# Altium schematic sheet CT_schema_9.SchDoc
size 308 x 210 mm
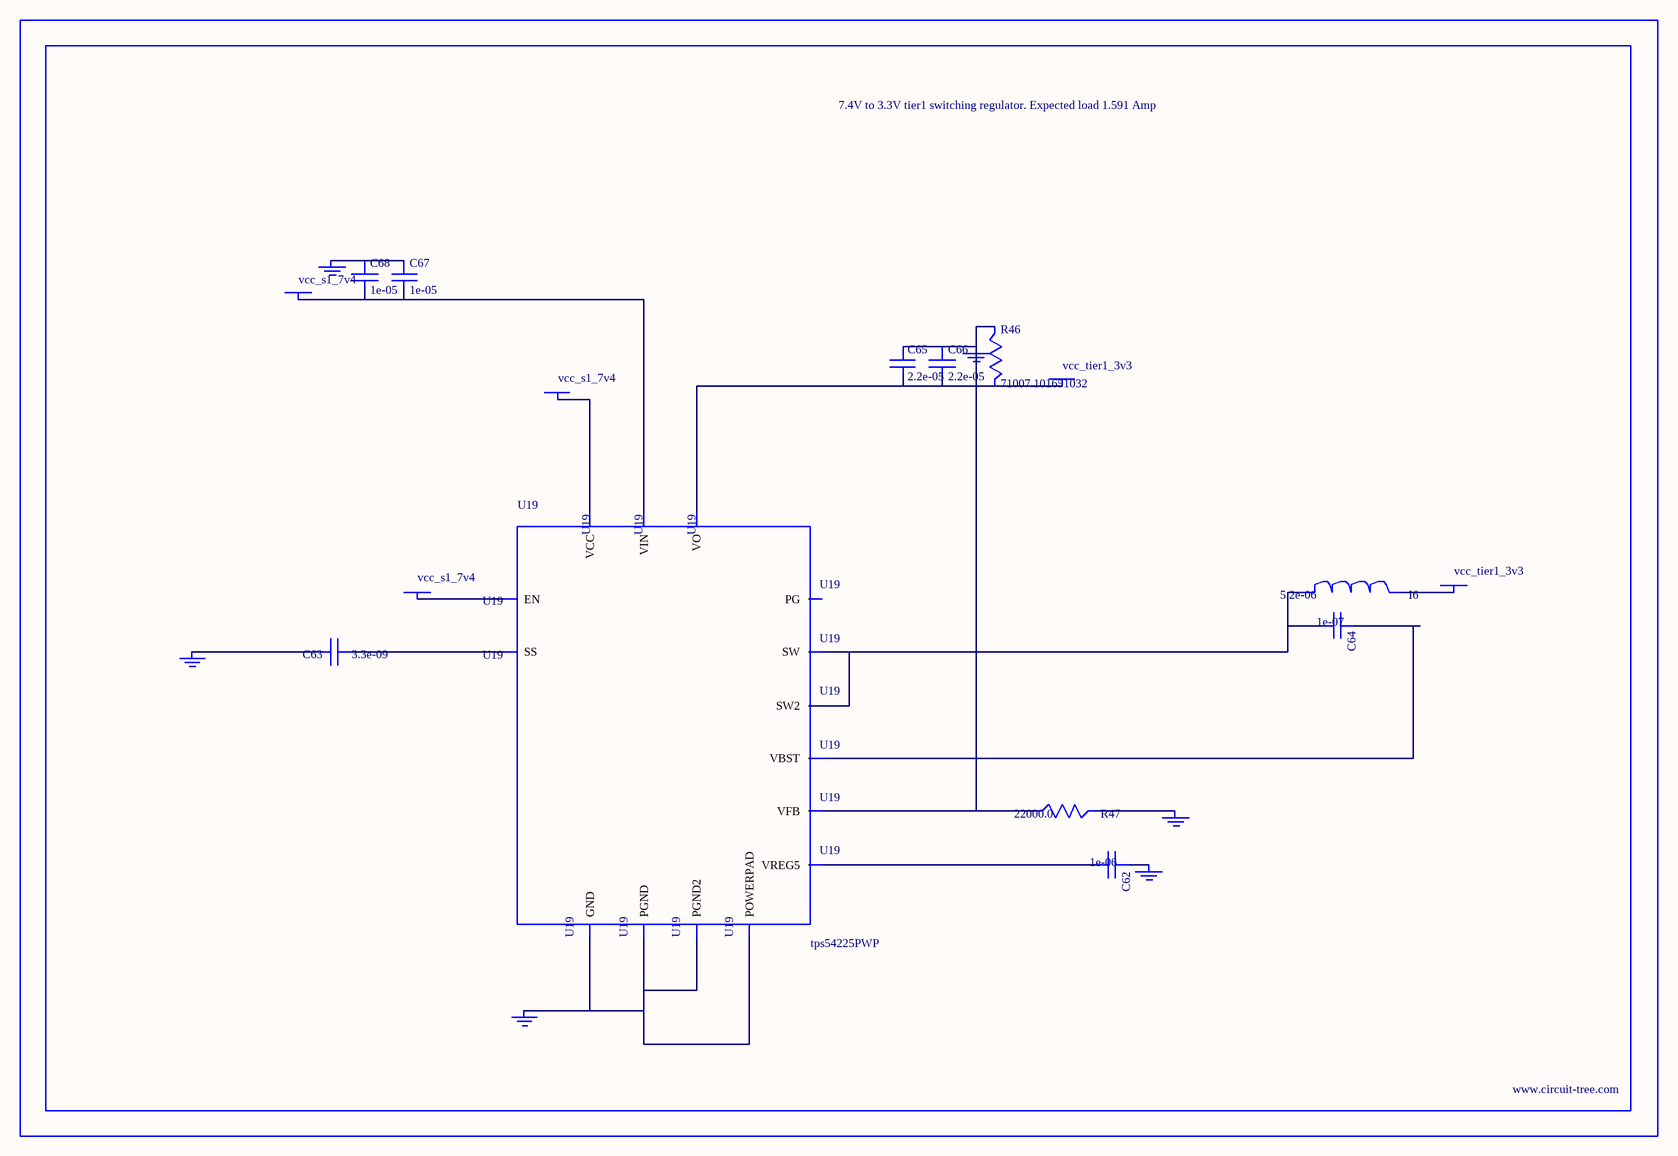
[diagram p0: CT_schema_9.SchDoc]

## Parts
BORDER8  (no value)
C62  1e-06  [C0603]
C63  3.3e-09  [C0402]
C64  1e-07  [C0402]
C65  2.2e-05  [C1210]
C66  2.2e-05  [C1210]
C67  1e-05  [C1206]
C68  1e-05  [C1206]
GND_INSTANCE_8_0  (no value)
GND_INSTANCE_8_1  (no value)
GND_INSTANCE_8_2  (no value)
GND_INSTANCE_8_3  (no value)
GND_INSTANCE_8_4  (no value)
GND_INSTANCE_8_5  (no value)
I6  5.2e-06  [DR1040]
POWER_INSTANCE_8_0  vcc_tier1_3v3
POWER_INSTANCE_8_1  vcc_s1_7v4
POWER_INSTANCE_8_2  vcc_tier1_3v3
POWER_INSTANCE_8_3  vcc_s1_7v4
POWER_INSTANCE_8_4  vcc_s1_7v4
R46  71007.101651032  [R0603]
R47  22000.0  [R0603]
U19  tps54225PWP  [HTSSOP14]

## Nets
NetC62_1: C62.1 GND_INSTANCE_8_2.0(GND)
NetC62_2: C62.2 U19.3(VREG5)
NetC63_1: C63.1 U19.4(SS)
NetC63_2: C63.2 GND_INSTANCE_8_3.0(GND)
NetC64_1: C64.1 U19.12(VBST)
NetC64_2: C64.2 I6.1 U19.10(SW) U19.11(SW2)
NetC65_1: C65.1 C66.1 GND_INSTANCE_8_0.0(GND) R46.1 R47.1 U19.2(VFB)
NetC65_2: C65.2 C66.2 POWER_INSTANCE_8_0.0(PWR) R46.2 U19.1(VO)
NetC67_1: C67.1 C68.1 GND_INSTANCE_8_5.0(GND)
NetC67_2: C67.2 C68.2 POWER_INSTANCE_8_3.0(PWR) U19.13(VIN)
NetGND_INSTANCE_8_1_0: GND_INSTANCE_8_1.0(GND) R47.2
NetGND_INSTANCE_8_4_0: GND_INSTANCE_8_4.0(GND) U19.5(GND) U19.8(PGND) U19.9(PGND2) U19.15(POWERPAD)
NetI6_2: I6.2 POWER_INSTANCE_8_2.0(PWR)
NetPOWER_INSTANCE_8_1_0: POWER_INSTANCE_8_1.0(PWR) U19.7(EN)
NetPOWER_INSTANCE_8_4_0: POWER_INSTANCE_8_4.0(PWR) U19.14(VCC)

Not connected (* = marked no-connect by the designer): U19 6(PG)

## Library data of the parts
BORDER8 = BORDER_PAGE8
C62 = C0603C105K3RACTU
C63 = C0402C332K3RAC
C64 = C0402C104K3RACTU
C65 C66 = GRM32ER61E226ME15L
C67 C68 = C1206C106K3RACTU
GND_INSTANCE_8_0-GND_INSTANCE_8_5 = GND
I6 = DR1040-5R2-R
POWER_INSTANCE_8_0-POWER_INSTANCE_8_4 = PWR
R46 = R46
R47 = RC0603JR-0722KL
